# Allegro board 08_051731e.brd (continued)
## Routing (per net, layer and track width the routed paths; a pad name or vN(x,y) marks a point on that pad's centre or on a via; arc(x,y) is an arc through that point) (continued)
+IN: length 8.2
  TOP w0.308: v1(39.33,44.46) 39.94,44.46 41.19,45.71 v1(43.25,45.71)
  BOTTOM w0.308: A2.3 v1(39.33,44.46) ; v1(43.25,45.71) 43.77,45.71 C53.1 R55.2
+VS: length 16.5
  BOTTOM w0.2: A1.5 40.25,49.06 39.95,49.37 R35.1
  BOTTOM w0.5: TP12.1 33.71,47.47 36.28,50.04 R35.1 C20.1 41.6,48.76 41.2,48.36 A1.6
-IN: length 9
  BOTTOM w0.308: A1.4 37.74,48.06 C54.1 37.28,47.73 36.14,46.58 36.14,44.7 36.39,44.44 36.39,42.87 35.88,42.36 R66.1
ARD_5V: length 10.4
  BOTTOM w0.6: P2.5 12.24,27.56 12.81,26.99 15.16,26.99 17.25,24.9 ARD5V.1
ARD_VIN: length 4.8
  BOTTOM w0.5: P2.8 16.11,19.94 ARDVIN.1
AREG_CAP: length 5.3
  TOP w0.2: C35.1 C34.1 33.6,34.4 U5.D14
CS_GN: length 59.7
  TOP w0.2: v1(60.5,14.8) 64.75,14.8 65.25,15.3 65.25,19.55 67.12,21.43 v1(67.12,23.43)
  BOTTOM w0.2: P5.10 60.25,59.88 60.25,57.8 60.62,57.43 62.08,57.43 63.5,56 63.5,54.68 66.47,51.7 66.47,45.58 67.5,44.55 68.16,44.55 P1.H13 67.12,42.54 v1(67.12,23.43) ; v1(60.5,14.8) 58.35,14.8 P4.3
CS_N: length 77.8
  TOP w0.14: 32.1,34 31.3,34
  TOP w0.2: 31.3,34 U5.E13 ; v1(61.21,30.43) v1(65.07,30.43) ; 32.1,34 33,34 34.1,32.9 37.9,32.9 38.8,33.8 52.55,33.8 60.88,42.13 60.88,46.43 63.38,48.93 v1(65.06,48.93) 67,48.93 v1(67.38,48.55)
  BOTTOM w0.2: P1.H10 68.06,47.87 v1(67.38,48.55) ; v1(61.21,30.43) P3.8 ; v1(65.07,30.43) 65.07,48.73 65.06,48.74 v1(65.06,48.93) 65.06,49.99 P5.1
DOUT_RDYB: length 89.6
  TOP w0.14: 28.9,31.7 28.88,31.73 28.88,32.61 28.9,32.64 28.9,33 28.5,33.4 U5.E10
  TOP w0.2: 28.9,31.7 28.9,31.23 31.68,28.45 37.35,28.45 40,31.1 59.26,31.1 59.86,31.7 v1(61.21,31.7) 68,31.7 68.85,32.55 71.12,32.55 v1(77.38,38.8)
  BOTTOM w0.2: v1(61.21,31.7) P3.6 ; P5.3 61.57,58.63 64.4,55.8 64.4,54.63 67.35,51.68 68.65,51.68 P1.H7 69.28,51.05 71.5,51.05 72.75,49.8 73.46,49.8 73.47,49.79 76.39,49.79 77.22,48.95 77.22,39.33 77.38,39.18 v1(77.38,38.8)
DRDY: length 108.5
  TOP w0.2: v1(72.25,46.55) 71.88,46.55 71.25,47.18 63.38,47.18 v1(62.88,46.68) ; v1(64,7.18) 64,12.05 71,19.05 v1(72,19.05) ; U5.E14 32.8,33.6 33.9,32.5 38.1,32.5 38.9,33.3 54.3,33.3 v1(54.5,33.5)
  BOTTOM w0.2: v1(54.5,33.5) 54.5,42 58.05,45.55 61.75,45.55 v1(62.88,46.68) 62.88,48.3 59,52.18 59,53.51 P5.7 ; v1(72.25,46.55) 72,46.3 v1(72,19.05) ; P4.6 61.28,7.18 v1(64,7.18)
  BOTTOM w0.25: P1.D11 73.68,46.55 v1(72.25,46.55)
DREG_CAP: length 2.5
  TOP w0.2: v2(30.15,32.1) 30.1,32.15 U5.F12
  BOTTOM w0.4: C36.1 v2(30.15,32.1)
GA0: length 19.6
  TOP w0.2: v1(75.88,17.43) 75.24,18.06 U4.2
  BOTTOM w0.2: P3.10 63.29,24.01 68.02,19.28 70.52,19.28 71.76,18.04 74.35,18.04 P1.C34 75.03,17.43 v1(75.88,17.43)
GA1: length 25.1
  TOP w0.2: U4.1 73.97,17.27 v1(72.88,16.18)
  BOTTOM w0.2: P1.D35 73.67,16.18 v1(72.88,16.18) 72.12,16.18 70.29,18.01 65.41,18.01 61.62,21.8 60.25,21.8 58.29,23.76 P3.9
GAIN0: length 28.6
  TOP w0.2: S2.1A v1(24.92,10.81) 19.5,16.23 19.5,31.05 21.25,32.8 U5.F1
  BOTTOM w0.2: R6.1 v1(24.92,10.81) R29.1
GAIN1: length 30.4
  TOP w0.2: S2.2A v1(27.46,10.81) 25.99,10.81 20,16.8 20,30.46 22.1,32.56 U5.F2
  BOTTOM w0.2: R30.1 v1(27.46,10.81) R5.1
GAIN2: length 32.4
  TOP w0.2: S2.3A v1(30,10.81) 29.26,11.55 26,11.55 20.5,17.05 20.5,30.05 22.9,32.45 U5.F3
  BOTTOM w0.2: R7.1 v1(30,10.81) R31.1
GPIO0: length 116
  TOP w0.2: v1(63.12,37.68) 62.75,38.05 62.75,44.43 64.12,45.8 R46.2 ; v1(63.38,27.3) 60.88,24.8 51,24.8 v1(49.5,23.3) ; U5.C9 v2(28.11,34.79) ; v1(24.92,13.8) 25.31,14.19 25.39,14.19 26.75,15.55 48.5,15.55 48.75,15.8 v1(49.5,15.8)
  BOTTOM w0.2: v1(49.5,23.3) v1(49.5,15.8) 49.5,9.3 56.64,2.16 P4.8 ; R6.2 v1(24.92,13.8) 25.85,14.73 25.85,28.19 24.62,29.41 24.62,32.59 25.04,33.01 27.17,33.01 27.8,33.64 27.8,34.48 v2(28.11,34.79) ; v1(63.12,37.68) 63.38,37.43 v1(63.38,27.3)
GPIO1: length 102.7
  TOP w0.2: v1(27.46,13.8) 27.85,14.19 27.89,14.19 28.75,15.05 v1(50.25,15.05) ; v1(50.25,22.55) 61.11,22.55 v1(64.48,25.93) ; R45.2 63.88,40.92 63.88,39.43 v1(64.47,38.83) ; U5.C10 v2(28.91,34.79)
  BOTTOM w0.14: 28.88,31.68 28.88,32.55
  BOTTOM w0.2: v1(64.48,25.93) 64.47,25.94 64.47,29.17 64.44,29.2 64.44,29.66 64.47,29.68 v1(64.47,38.83) ; 28.88,31.68 28.88,29.3 26.74,27.17 26.74,14.52 v1(27.46,13.8) R5.2 ; v1(50.25,22.55) v1(50.25,15.05) 50.25,10.55 56.1,4.7 P4.7 ; 28.88,32.55 28.2,33.23 28.2,34.08 v2(28.91,34.79)
GPIO2: length 114.4
  TOP w0.14: 32.1,35.6 29.7,35.6 U5.C11
  TOP w0.2: v1(63.91,26.68) 61.16,23.93 51.62,23.93 v1(51,23.3) ; 32.1,35.6 33,36.5 33.7,36.5 34,36.8 37.3,36.8 39.2,34.91 52.11,34.91 v1(56.1,38.9) ; R44.2 63.75,42.55 v1(63.75,41.93) 63.38,41.55 63.38,38.3 v1(63.88,37.8) ; v1(51,13.55) 49.25,13.55 48.25,14.55 30.75,14.55 v1(30,13.8)
  BOTTOM w0.2: v1(56.1,38.9) 58,40.8 62.62,40.8 v1(63.75,41.93) ; v1(51,23.3) v1(51,13.55) 55.12,13.55 56.35,12.32 P4.4 ; v1(63.88,37.8) 63.91,37.76 63.91,27.55 63.93,27.53 63.93,27.07 63.91,27.05 v1(63.91,26.68) ; v1(30,13.8) R7.2
GPIO3: length 50.9
  TOP w0.14: U5.D10 28.1,34 28.1,32.65 28.1,32.65 28.1,32.64 27.99,32.53 27.99,31.31
  TOP w0.2: 27.99,31.31 31.2,28.1 37.6,28.1 39.9,30.4 v2(55.7,30.4) ; v1(64.5,40.55) R48.2
  BOTTOM w0.2: v1(64.5,40.55) 64.09,40.14 63.1,40.14 63.05,40.19 59.03,40.19 55.7,36.85 v2(55.7,30.4)
IN+: length 18.8
  TOP w0.4: R53.1 R15.1 9.37,32.3 8,30.93 P7.3 J3.1
IN-: length 18.6
  TOP w0.4: J4.1 P7.1 9,38.55 10.25,37.3 R14.1 R54.1
IN-N: length 8.2
  TOP w0.2: U5.C1 16.17,35.2 15.82,35.55 15,35.55 C17.1
  TOP w0.5: C17.1 R14.2
IN-P: length 8.2
  TOP w0.2: U5.D1 16.06,34.4 15.71,34.05 C17.2
  TOP w0.5: R15.2 C17.2
LDO_5V: length 29.5
  TOP w0.25: U5.F7 25.85,32.53 v1(25.5,32.05) ; U5.F6 25.3,32.25 v1(25.5,32.05) ; v1(25.5,32.05) 25.56,32 26.09,32 U5.F8
  TOP w0.8: E4.2 v2(24.62,28) E5.2
  L3_PWR w0.8: v2(26.5,40.8) 25.7,40.8 24.43,39.54 24.43,37.27 24.95,36.76 24.95,32.6 v1(25.5,32.05) 24.62,31.18 v2(24.62,28)
  BOTTOM w0.8: R27.2 33.37,40.85 E3.2 E2.2 27.57,40.8 v2(26.5,40.8)
LDO_OUT: length 9.6
  BOTTOM w0.5: R27.1 34.32,39.25 34.71,38.85 36.39,38.85 40.2,35.04 R23.1
M0: length 32.1
  TOP w0.2: U5.A7 v1(25.3,37.6)
  BOTTOM w0.2: v1(25.3,37.6) U5.A7 26.1,36.7 27.56,35.24 31.03,35.24 32.81,33.46 32.81,28.86 31.16,27.21 31.16,25.11 31.97,24.3 R16.2 32,23.21 31.95,23.17 31.95,20.1 32.54,19.51 R11.2
M1: length 31.3
  TOP w0.2: U5.A8 v1(26.9,37.6)
  BOTTOM w0.2: v1(26.9,37.6) 26.9,36.96 27.92,35.94 31.35,35.94 33.58,33.72 33.58,28.26 32.93,27.61 32.93,25.1 33.72,24.3 R17.2 33.75,21.6 35.08,20.27 R10.2
MCLK: length 21.2
  TOP w0.2: 33.5,31.3 32,32.8 U5.F14
  TOP w0.25: 33.5,31.3 34.65,31.3 v1(34.9,31.05)
  BOTTOM w0.25: v1(34.9,31.05) 34.95,31.1 R37.2 40.55,31.1 R38.1 40.7,30.95 40.7,27.9 44,24.6 J1.1
MCLK_FMC: length 47
  TOP w0.2: v1(51.25,36.95) 51.25,40.05 61.88,50.68 68.38,50.68 v1(70.62,52.93) 70.62,53.43 70.13,53.92 R47.2
  BOTTOM w0.2: v1(51.25,36.95) 51.25,36.06 50.36,35.17 50.36,33.01 49.47,32.12 39.98,32.12 39.5,32.6 R37.1
  BOTTOM w0.25: v1(70.62,52.93) 69.94,52.93 P1.G6
MCLK_RETURN: length 1.8
  TOP w0.2: v1(68.06,55.49) 69.19,55.49 R47.1
  BOTTOM w0.25: P1.H4 v1(68.06,55.49)
REF_N: length 25.1
  TOP w0.14: 31.3,37.44 31.3,36.4
  TOP w0.2: 31.8,37.94 31.3,37.44 ; 31.3,36.4 U5.B13
  TOP w0.308: v1(39.69,41.27) 40.34,41.27 R22.1 40.98,44.45 41.48,44.95 v1(43.25,44.95)
  TOP w0.318: 31.8,37.94 33.6,39.74 R36.2 33.62,39.88 34.25,40.5 34.47,40.5 35.35,41.38 C27.2 36.14,41.38 36.25,41.27 v1(39.69,41.27)
  BOTTOM w0.308: v1(43.25,44.95) 43.76,44.95 C53.2 ; v1(39.69,41.27) 39.17,41.27 C26.2 38.8,42.66 40.25,44.11 40.25,45.66
REF_P: length 15.8
  TOP w0.2: U5.B14 32.71,37.01 32.71,37.96
  TOP w0.308: R21.2 40.96,40.12 40.58,40.5 v1(39.69,40.5)
  TOP w0.318: v1(39.69,40.5) 36,40.5 C27.1 35.35,39.88 34.45,38.98 33.73,38.98 32.71,37.96
  BOTTOM w0.308: R66.2 R67.2 C26.1 39.17,40.5 v1(39.69,40.5)
RESET_ADC: length 110.6
  TOP w0.14: U5.D11 28.9,34 28.9,33.44 29.14,33.2 29.46,33.2 29.7,32.96 29.7,32.64 29.73,32.61 29.73,31.47
  TOP w0.2: v1(66.38,35.8) 65.75,35.8 65.25,36.3 R41.2 ; S1.4 v1(54.08,12.8) ; S1.4 54.86,14.66 v1(55.25,15.05) ; S1.4 C44.1 ; v1(66.38,32.3) 59.5,32.3 58.8,31.6 39.8,31.6 37.1,28.9 32.3,28.9 29.73,31.47 ; v1(66.38,22.05) 64.5,20.18 64.5,16.43 64.12,16.05 v1(63.75,16.05)
  BOTTOM w0.2: v1(55.25,15.05) 56.25,16.05 v1(63.75,16.05) ; v1(54.08,12.8) 54.08,12.22 56.52,9.78 P4.5 ; P5.8 60.25,54.8 62.55,54.8 65.92,51.43 65.92,44.73 66.38,44.27 v1(66.38,35.8) v1(66.38,32.3) v1(66.38,22.05)
RESET_FPGA: length 6.7
  TOP w0.2: v1(70.5,41.55) 70,41.55 66.75,38.3 R41.1
  BOTTOM w0.2: P1.G15 69.95,41.55 v1(70.5,41.55)
SCL: length 47.4
  TOP w0.2: v1(75.8,22.47) 76.14,22.47 76.5,22.83 76.5,24.46 U4.6 76.62,24.58 v1(76.62,26.18) ; v1(67.33,49.8) 63.12,49.8 v1(60.2,46.87)
  BOTTOM w0.2: v1(76.62,26.18) 76.62,28.79 76.91,29.07 76.91,29.71 76.75,29.86 76.75,47.21 76.75,47.21 76.75,47.93 76.16,48.52 73.47,48.52 73.47,48.53 72.78,48.53 71.51,49.79 68.39,49.79 68.38,49.8 v1(67.33,49.8) ; P3.1 v1(60.2,46.87) ; P1.C30 v1(75.8,22.47)
SCLK: length 94.1
  TOP w0.14: 30.8,32.12 30.5,32.42 30.5,32.96 30.26,33.2 29.9,33.2 29.5,33.6 U5.E11
  TOP w0.2: 30.8,32.12 31.52,31.4 32,31.4 33,30.4 37.9,30.4 39.6,32.1 58.5,32.1 58.52,32.07 62,35.55 v1(62.5,35.55) 65.09,35.55 67.59,33.05 70.75,33.05 v1(77.88,40.18)
  BOTTOM w0.2: P1.D8 74.38,51.06 76.12,51.06 77.01,50.17 77.04,50.17 77.62,49.59 77.62,49.21 77.63,49.21 77.63,40.42 v1(77.88,40.18) ; P5.4 61.63,61.17 62.75,60.05 62.75,58.8 65.17,56.38 65.17,54.75 67.6,52.33 71.19,52.33 73.11,50.41 ; P3.5 61.99,36.71 62.5,36.2 v1(62.5,35.55)
  BOTTOM w0.25: P1.D8 73.11,50.41
SDA: length 43.2
  TOP w0.2: v1(63.84,44.33) 63.84,44.4 64.38,44.93 67.25,44.93 67.56,44.62 v1(78.5,44.62) ; v1(77.82,26.24) 77.82,24.5 U4.5 77.75,24.44 77.75,22.93 76.03,21.2 v1(75.65,21.2)
  BOTTOM w0.2: v1(77.82,26.24) 78.12,26.55 78.12,37.8 78.5,38.18 v1(78.5,44.62) ; P1.C31 v1(75.65,21.2) ; P3.2 v1(63.84,44.33)
SDI: length 73
  TOP w0.14: 32.1,33.2 30.7,33.2 30.3,33.6 U5.E12
  TOP w0.2: P5.2 68.04,56.09 68.25,56.3 70.88,56.3 71.25,55.93 71.25,49.8 v1(70.59,49.14) 69.34,49.14 68,47.8 63.12,47.8 61.5,46.18 61.5,36.05 v1(58.25,32.8) 39.5,32.8 38.8,32.1 33.7,32.1 32.6,33.2 32.1,33.2
  BOTTOM w0.2: P3.7 58.25,31.67 v1(58.25,32.8)
  BOTTOM w0.25: P1.G9 v1(70.59,49.14)
SYNC_IN: length 114.7
  TOP w0.14: U5.D12 30.5,34.8 32.1,34.8
  TOP w0.2: 32.1,34.8 33.4,34.8 34,35.4 34,36.1 34.3,36.4 36.95,36.4 38.95,34.4 v1(51.4,34.4) ; v1(71.75,48.55) 71.75,48.56 71.75,56.17 70.61,57.32 67.64,57.32 67.12,56.8 63.38,56.8 62.75,57.43 60.16,57.43 P5.9 ; v1(65,23.43) 63.5,21.93 v1(63.5,17.43) ; v1(51.4,29.4) 64.97,29.4 v1(65,29.43) v1(76.25,29.43) ; U5.D12 v2(29.7,34)
  BOTTOM w0.2: v1(65,23.43) 65,25.66 65.04,25.7 65.04,26.16 65,26.19 v1(65,29.43) ; v1(63.5,17.43) 61.24,17.43 P4.2 ; v1(71.75,48.55) 71.75,47.93 72.45,47.22 74.35,47.22 P1.C10 75.56,47.87 76.25,47.18 76.25,43.01 76.26,43.01 76.26,42.59 76.25,42.59 v1(76.25,29.43) ; v1(51.4,34.4) v1(51.4,29.4)
  BOTTOM w0.4: v2(29.7,34) 29.55,34 29.45,33.9 R40.2
UNNAMED_3_ADAQ77681V2_I305_M0ADC: length 19.2
  TOP w0.14: 26.5,36.4 26.5,37.2
  TOP w0.2: U5.B7 26.5,36.4 ; 26.5,37.2 v1(26.1,37.6)
  BOTTOM w0.2: v1(26.1,37.6) 26.49,37.21 26.49,36.87 27.77,35.59 31.19,35.59 33.19,33.59 33.19,28.51 32,27.32 R16.1
UNNAMED_3_ADAQ77681V2_I305_M1AD: length 17.8
  TOP w0.14: 27.3,36.4 27.3,37.1
  TOP w0.2: 27.3,37.1 v1(27.75,37.55) ; U5.B8 27.3,36.4
  BOTTOM w0.2: v1(27.75,37.55) 28.3,37 30.8,37 33.96,33.84 33.96,28 33.75,27.8 R17.1
UNNAMED_3_ADAQ77681V2_I305_SYNC: length 1
  TOP w0.2: U5.D13 v2(30.49,33.99)
  BOTTOM w0.4: v2(30.49,33.99) 30.76,33.99 R40.1
UNNAMED_3_ADP2301_I180_FB: length 2.9
  TOP w0.6: U1.3 25.7,55.84 R3.1 R2.2
UNNAMED_3_ADP7182V5_I211_ADJ: length 7.8
  TOP w0.25: 20,50.3 20.25,50.05 20.25,48.43 ; 19.74,52.06 U3.2
  TOP w0.6: 19.74,52.06 19.74,51.29 R26.1 20,50.55 20,50.3 ; R28.1 18.25,47.55 R25.1 19.5,47.67 20.25,48.43
UNNAMED_3_ADR45XX_I443_GND: length 12.3
  TOP w0.2: C39.2 45.91,39.97
  TOP w0.308: C39.2 45.91,40.27 45.91,41.59 45.6,41.9 R22.2 ; 45.91,39.97 v1(45.91,39.23)
  BOTTOM w0.308: v1(45.91,39.23) 45.47,38.8 45.21,38.8 44.39,37.99 U6.4 43.5,37.2 43,36.69 C40.2 R49.2
UNNAMED_3_ADR45XX_I443_VIN: length 10.6
  BOTTOM w0.5: C40.1 41.36,36.54 42.14,35.76 42.16,35.76 42.86,35.07 R23.2 R60.2 45.67,33.65 46.93,34.9 U6.2
UNNAMED_3_ADR45XX_I443_VOUT: length 8.7
  TOP w0.308: v1(44.4,39.23) 44.4,40.12 C39.1 R21.1
  BOTTOM w0.308: R55.1 U6.6 45.66,40.84 45.67,40.83 45.67,40.5 v1(44.4,39.23)
UNNAMED_3_CAP_I190_N1: length 9.1
  TOP w0.25: 33,57.55 32.29,56.84 32.29,54.01 32.5,53.8 33.75,53.8 35.25,55.3 U2.6
  TOP w0.3: U2.2 35.38,57.3
UNNAMED_3_CAP_I191_N1: length 9.4
  TOP w0.25: 39.5,57.3 39.75,57.3 ; 42,57.43 42.88,56.55 42.88,53.93 42.75,53.8 41.25,53.8 39.75,55.3 U2.15
  TOP w0.3: U2.19 39.5,57.3
UNNAMED_3_CAP_I193_N2: length 1.5
  TOP w0.3: U2.4 34.63,56.3
UNNAMED_3_CAP_I209_N1: length 1.8
  TOP w0.6: C16.1 R26.2
UNNAMED_3_IND_I195_N2: length 0.5
  TOP w0.3: U2.24 36.75,58.8 36.62,58.93
UNNAMED_3_IND_I196_N2: length 0.5
  TOP w0.3: U2.21 38.25,58.8 38.38,58.93
UNNAMED_3_LINLT3095_I198_RT: length 1.7
  TOP w0.3: U2.17 40.62,56.3
UNNAMED_3_RES_I169_N1: length 1.8
  TOP w0.2: S1.3 R24.1
UNNAMED_3_RES_I306_N2: length 2.6
  TOP w0.508: R34.2 24.96,17.9 S2.1B
UNNAMED_3_RES_I311_N1: length 3.6
  TOP w0.2: v1(32.54,10.81) S2.4A
  BOTTOM w0.2: R32.1 v1(32.54,10.81) R11.1
UNNAMED_3_RES_I312_N1: length 3.6
  TOP w0.2: v1(35.08,10.81) S2.5A
  BOTTOM w0.2: R10.1 v1(35.08,10.81) R33.1
UNNAMED_3_RES_I360_N2: length 2
  BOTTOM w0.25: R38.2 Y1.3
UNNAMED_3_RES_I424_N2: length 2.6
  TOP w0.508: R18.2 27.5,17.9 S2.2B
UNNAMED_3_RES_I425_N2: length 2.6
  TOP w0.508: S2.3B 30.04,17.9 R19.2
UNNAMED_3_SWITCH5_I307_N7: length 5.2
  TOP w0.508: R20.2 32.58,17.9 S2.4B S2.5B
UNNAMED_6_CN8PA_I42_N1: length 4.7
  BOTTOM w0.2: TP9.1 53.64,19.94 P4.1
UNNAMED_6_CN160PCDGHV2_I2_LA11P: length 2
  TOP w0.2: v1(67.75,40.3) 67.5,40.55 R48.1
  BOTTOM w0.25: v1(67.75,40.3) 68.6,40.3 P1.H16
UNNAMED_6_CN160PCDGHV2_I2_PRSNT: length 1.9
  TOP w0.2: v1(68.02,58.03) 66.77,58.03 R13.2
  BOTTOM w0.25: P1.H2 v1(68.02,58.03)
UNNAMED_6_CN160PCDGHV2_I8_LA08P: length 5.3
  TOP w0.2: v1(70.75,45.3) 70,45.3 69.25,46.05 67,46.05 R46.1
  BOTTOM w0.25: v1(70.75,45.3) 69.95,45.3 P1.G12
UNNAMED_6_CN160PCDGHV2_I17_3P3V: length 13.6
  TOP w0.5: R56.2 v1(71.75,13.55)
  BOTTOM w0.5: 71.75,12.32 71.76,12.31 P1.D38 P1.C39 ; 71.75,12.32 v1(71.75,13.55) 71.75,14.05 72.5,14.8 73.68,14.8 P1.D36 ; 71.75,12.32 71.75,10.55 72.5,9.8 73.7,9.8 P1.D40
UNNAMED_6_CN160PCDGHV2_I17_LA09: length 7.2
  TOP w0.2: v1(73,42.8) 72.43,42.23 66.82,42.23 R45.1
  BOTTOM w0.25: P1.D14 73.72,42.8 v1(73,42.8)
UNNAMED_6_CN160PCDGHV2_I21_LA10: length 10.3
  TOP w0.2: R44.1 70.88,44.05 71.5,43.43 74,43.43 74.62,42.8 v1(75.75,42.8)
  BOTTOM w0.25: P1.C14 75.01,42.8 v1(75.75,42.8)
UNNAMED_6_ICM24CXX_I24_VCC: length 4.9
  TOP w0.5: U4.8 73.97,23.83 73.47,23.33 72.75,23.33 72,22.58 R58.2 R59.1
VOUT: length 9.7
  BOTTOM w0.308: 41.2,45.66 41.2,46.55 40.9,46.85 38.66,46.85 37.53,45.73 C54.2 37.41,44.86 37.03,44.48 37.03,42.92 37.41,42.54 R67.1

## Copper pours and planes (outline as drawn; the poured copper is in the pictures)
3V3 on TOP (solid shape): 55.75,65.8 55.75,56.3 54.25,56.3 51.75,58.8 51.75,60.8 51.5,61.05 51,61.05 50.75,61.3 50.75,63.3 51.5,64.05 51.5,66.05 52,66.55 55,66.55
3V3 on TOP: 24.45,62.8 24.52,62.98 24.7,63.05 28.25,63.05 28.43,62.98 28.5,62.8 28.5,59.8 28.43,59.62 28.25,59.55 24.7,59.55 24.52,59.62 24.45,59.8
3V3 on TOP: 37.25,58.18 37.25,59.05 36.62,59.68 36.62,64.3 36.12,64.8 31.5,64.8 31.5,67.3 32.5,68.3 44.38,68.3 45.38,67.3 45.38,65.18 43.5,65.18 43.12,64.8 38.5,64.8 38,64.3 38,59.3 37.75,59.05 37.75,58.18
3V3 on L3_PWR: 25.75,59.55 29.5,59.55 31.5,61.55 49.25,61.55 56.25,54.55 56.25,28.8 54.75,27.3 46,27.3 45.5,26.8 45.5,25.8 46,25.3 54.75,25.3 55.5,24.55 55.5,18.3 52.75,15.55 40.75,15.55 39.25,17.05 39.25,23.3 34.12,28.43 27.5,28.43 27.5,26.41 22.7,21.6 16.2,21.6 12.2,25.6 12.2,29.2 11.7,29.7 10,29.7 9.25,28.95 9.25,16.55 15.75,10.05 66,10.05 68.5,12.55 68.5,61.8 62.5,67.8 30.75,67.8 25.75,62.8
15V on TOP (solid shape): 43.12,51.43 45.25,51.43 45.25,48.43 44.5,47.68 43.12,47.68 41,49.8 41,52.18 42.38,52.18
-15V on TOP: 16.5,48.17 16.43,48.35 16.25,48.43 15.38,48.43 15.2,48.35 15.12,48.17 15.12,44.66 15.14,44.56 15.2,44.48 16.55,43.12 16.63,43.07 16.73,43.05 22.39,43.05 22.49,43.07 22.57,43.12 22.93,43.48 22.98,43.56 23,43.66 23,44.57 22.98,44.67 22.93,44.75 21.45,46.23 21.37,46.28 21.27,46.3 17.11,46.3 17.01,46.32 16.93,46.37 16.57,46.73 16.52,46.81 16.5,46.91
-16V on TOP: 25.62,64.05 25.8,64.12 25.88,64.3 25.88,66.42 25.8,66.6 25.62,66.68 16.95,66.68 16.85,66.66 16.77,66.6 13.32,63.16 13.27,63.07 13.25,62.98 13.25,56.16 13.27,56.06 13.32,55.98 14.05,55.25 14.13,55.19 14.23,55.17 18.68,55.17 18.86,55.1 18.94,54.92 18.94,53.5 19.01,53.32 19.19,53.25 19.98,53.25 20.16,53.18 20.24,53 20.24,52.44 20.31,52.26 20.49,52.19 20.9,52.19 21.08,52.26 21.15,52.44 21.15,53.99 21.08,54.17 20.9,54.24 19.5,54.24 19.32,54.31 19.25,54.49 19.25,56.82 19.23,56.92 19.17,57 18.95,57.23 18.86,57.28 18.77,57.3 16.48,57.3 16.38,57.32 16.3,57.37 15.57,58.1 15.52,58.18 15.5,58.28 15.5,62.69 15.52,62.79 15.57,62.87 17.44,64.74 17.52,64.79 17.62,64.81 18.88,64.81 19.06,64.74 19.13,64.56 19.13,63.3 19.15,63.2 19.21,63.12 20.13,62.2 20.18,62.12 20.2,62.02 20.2,61.98 20.27,61.8 20.45,61.72 20.64,61.72 20.82,61.8 20.9,61.98 20.9,63.8 20.97,63.98 21.15,64.05
GND_SIGNAL on TOP (solid shape): 41.25,55.18 42.12,55.18 42.12,54.43 41.25,54.43 40.25,55.43 40.25,55.55 40.88,55.55
GND_SIGNAL on TOP: 80.25,68.3 0.5,68.3 0.5,2.55 7.25,2.55 7.25,0.55 80.25,0.55 ; 18 cut-outs
GND_SIGNAL on BOTTOM: 80.25,68.3 0.5,68.3 0.5,2.55 7.25,2.55 7.25,0.55 80.25,0.55 ; 9 cut-outs
GND_SIGNAL on L2_GND, L3_PWR: 80.25,68.3 0.5,68.3 0.5,2.55 7.25,2.55 7.25,0.55 80.25,0.55
UNNAMED_3_ADP7182V5_I211_VOUT on TOP: 17.18,52.1 17.26,52.16 17.36,52.18 18.15,52.18 18.33,52.25 18.4,52.43 18.4,52.7 18.47,52.88 18.65,52.95 19.25,52.95 19.25,52.17 19.23,52.07 19.17,51.99 18.82,51.64 18.77,51.56 18.75,51.46 18.75,49.95 18.82,49.77 19,49.7 19.62,49.7 19.62,48.9 15.38,48.9 15.2,48.97 15.12,49.15 15.12,49.94 15.14,50.04 15.2,50.12
UNNAMED_3_CAP_I190_N1 on TOP (solid shape): 35,58.43 35,57.68 35.12,57.55 35.5,57.55 35.75,57.3 35.5,57.05 33.12,57.05 32.88,57.3 32.88,58.8 34.62,58.8
UNNAMED_3_CAP_I191_N1 on TOP (solid shape): 42.12,57.3 41.88,57.05 39.5,57.05 39.25,57.3 39.5,57.55 39.75,57.55 40,57.8 40,58.43 40.38,58.8 42.12,58.8
UNNAMED_3_CAP_I193_N2 on TOP (solid shape): 35.62,56.43 35.62,56.3 34.88,56.3 34.5,55.93 33,55.93 33,56.68 35.38,56.68
UNNAMED_3_CAP_I203_N1 on TOP (solid shape): 36.75,52.8 37.38,52.18 37.38,47.18 36.12,47.18 36.12,53.18 36.65,53.7 36.75,53.7
UNNAMED_3_CAP_I204_N1 on TOP (solid shape): 38.88,53.3 38.88,51.18 39,51.05 39,47.18 37.88,47.18 37.88,52.18 38.25,52.55 38.25,53.8 38.38,53.8
UNNAMED_3_IND_I195_N2 on TOP (solid shape): 36.25,59.55 36.75,59.05 36.75,58.3 36.62,58.3 35.38,59.55 35.38,61.18 35.12,61.43 32,61.43 31.88,61.55 31.88,63.3 36.25,63.3
UNNAMED_3_IND_I196_N2 on TOP (solid shape): 43,61.43 39.62,61.43 39.38,61.18 39.38,59.43 38.25,58.3 38.25,59.05 38.5,59.3 38.5,63.3 43,63.3
UNNAMED_3_LINLT3095_I198_OUT1 on TOP (solid shape): 36.25,53.8 35.75,53.3 35.75,51.18 34.5,51.18 34.5,52.55 35.12,53.18 35.12,53.55 35.62,54.05 35.62,54.18 35.75,54.3 36.25,54.3
UNNAMED_3_LINLT3095_I198_OUT2 on TOP (solid shape): 40.25,53.18 40.25,51.3 39.25,51.3 39.12,51.43 39.12,53.43 38.75,53.8 38.75,54.3 39.12,54.3
UNNAMED_3_LINLT3095_I198_RT on TOP (solid shape): 42.12,55.93 40.75,55.93 40.38,56.3 39.5,56.3 39.5,56.55 39.62,56.68 42.12,56.68

Small or netless copper shapes (teardrops, artwork), in the pictures only: 3 on TOP

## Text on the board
BOTTOM: 4
Ref Des/Assembly Bottom: SEE DETAIL A | 2 | 3 | 4 | 1 | TOP VIEW | DETAIL A | BOTTOM VIEW | YSML126W98H31-ASSY-DETAIL | CHAMFER
Ref Des/Silkscreen Bottom: SECONDARY SIDE | 08-051731 REV E Z | SCL | GPIO0
User.Comments: SEE NOTE #5 | 1 | C | A | SIDE OF THE BOARD. | 1.    BOARD ACCEPTABILITY PER ANALOG DEVICES, INC. SPECIFICATION | TST00119 (LATEST REVISION). | 4.    RoHS COMPLIANCE: ASSEMBLY VENDOR SHOULD ASSURE COMPLIANCE | 2.    REPAIRS PER IPC-7711/21(LATEST REVISION) ARE ALLOWED. | 3.    REPAIRS ARE NOT ALLOWED IN SOLDERMASK FREE AREAS ON EITHER | 5.    FROM SECONDARY SIDE, INSERT TWO 16MM STANDOFFS AT HOLES ON TOP | ASSEMBLY NOTES: | WITH LEAD-FREE AND RoHS PCB ASSEMBLY STANDARDS (EU RoHS | DIRECTIVE 2002/95/EC). | LEFT & BOTTOM LEFT CORNERS(STAND ON SECONDARY SIDE, NUT ON PRIMARY SIDE)
TOP: 1
Ref Des/Silkscreen Top: IN+ | IN- | GND | EV-ADAQ7768-1F1ZU6 | 08-051731 REV E Z | PRIMARY SIDE | LO | HI | MCLK | 3V3 | RESET | CS_N | C | A | GAIN0 | GAIN1 | GAIN2 | M0_FDA | M1_FDA
L2_GND: 2
L3_PWR: 3
DIMENSION: - | " | (REF) | +.0508 MM/-0 MM | DIA MAX      SEE NOTE 11
XSECTION_CHART: 1.6mm +/-10% | 4 LAYER STACKUP | Primary Side Silkscreen | Primary Side Soldermask | Primrary Side - (Layer-1) 0.5 Oz | 0.10414 mm FR4 | L2-GND PLANE (Layer-2) 1 Oz. | FR4 Prepreg | L3 - Gnd/Power (layer-3) 1 Oz. | Secondary Side - (Layer-4) 0.5 Oz. | Secondary Side Soldermask | Secondary side Silkscreen
DISPLAY_TOP: CHARACTERISTIC IMPEDANCE NOTES - Not Applicable to this layout | Primary Side - 100 Ohm +/- 10% Differential Impedance (using Layer-2 as Ground reference Layer) | Artwork Line And Width Spacings for Diff Pairs: | Primary & Secondary Sides - 50 Ohm +/- 10% Singel Ended Impedance. | Artwork Line for single Ended Impedance: | 0.127 : 0.254 : 0.127 (Trace/gap/trace) in mm. | 0.1524mm (Layer-1, using Layer-2 as ground reference layer. | 0.1524mm (Layer-2, using Layer-3 as ground reference layer.
User.14: L2 GND | 08-      -07
User.15: L3 PWR | 08-      -08
User.21: AS PER ECR-089465 | AS PER ECR-094813 | AS PER ECR-098266 | AS PER ECR-111608 | 25OCT19 | 14MAY20 | 13OCT20 | 23NOV22 | J.VILLANU | K.HOFFMAN | C.AURE | C | D | D1 | E
User.24: FABRICATION NOTES: | 1. Material: 4 Layer FR4 glass epoxy laminate 1.6mm +/- 10%. material to be RoHS compliant. | 2. Plated thru holes and conductive pattern electroplated with 25uM min. thick copper. | 3. Processing tolerence: | 4. Warp and twist within 0.1875mm per 25mm (0.75%) | 5. Dimensions are for the finished part. | 6. SOLDERMASK: liquid Photo Imeagable soldermask over bare copper (SMOBC), | 7. SCREENING: Screen component outlines and nomenclature using indelible white ink on both sides. | 8. Electrically test 100%. | 9. Break all sharp edges 0.35mm Radius max. | 10. Manufacturer UL and Date codes on the bottom side silkscreen as indicated. | 11. Via-in-pad. Any via in pad must be filled and levelled. | Board to be fabricated per IPC-6012A, CLASS 2. | Terminal areas and plated thru holes to be ENIG plated. | A. Conductive pattern front to back registration within 0.125mm total. | B. Minimum annual ring surrounding holes 0.05mm. | C. Finished conductive pattern to be within 0.05mm of true size. | D. Minimumfeature size 0.2mm | E. Minimum air gap 0.12mm | colour GREEN both sides using the pattern provided. No mask is permitted on the terminal areas. | Soldermask to etch registration within 0.125mm total. | Nomenclature shall be legible. Screen to etch registration within 0.15mm total. | 1 | FABRICATION | 09-051731 | E
User.25: FIGURE | SIZE | 0.2032 | 0.2489 | 0.4089 | 0.5105 | 1.0211 | 1.1405 | 1.27 | 1.5189 | 3.175 | PLATED | NON-PLATED | FINISHED HOLES IN MM | ALL UNITS ARE IN MILLIMETERS | QTY | 20 | 299 | 13 | 4 | 12 | 15 | 5 | 2 | TOLERANCE/NOTES
